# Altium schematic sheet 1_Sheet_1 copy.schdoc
size 302 x 215 mm; Name: A_A4; Symbol: a_a4; Device: A_A4; @Project Name: Quectel_EC200U_Board; REV: 1.1; Date: 11-07-24; Sheet: 1/1; Draw By: Anusha; Company: FervidSmart Solutions; Convert to PCB: yes; Add into BOM: yes; @Page No: 1; @Page Count: 3; @Schematic Name: Quectel_EC200U_Boost_Board; @Board Name: Quectel_EC200U_Boost_Board; @Update Date: 2025-06-19; @Create Time: 06:39:23; @Update Time: 12:09:43; @Page Name: Sheet_1 copy; @Create Date: 2025-06-19
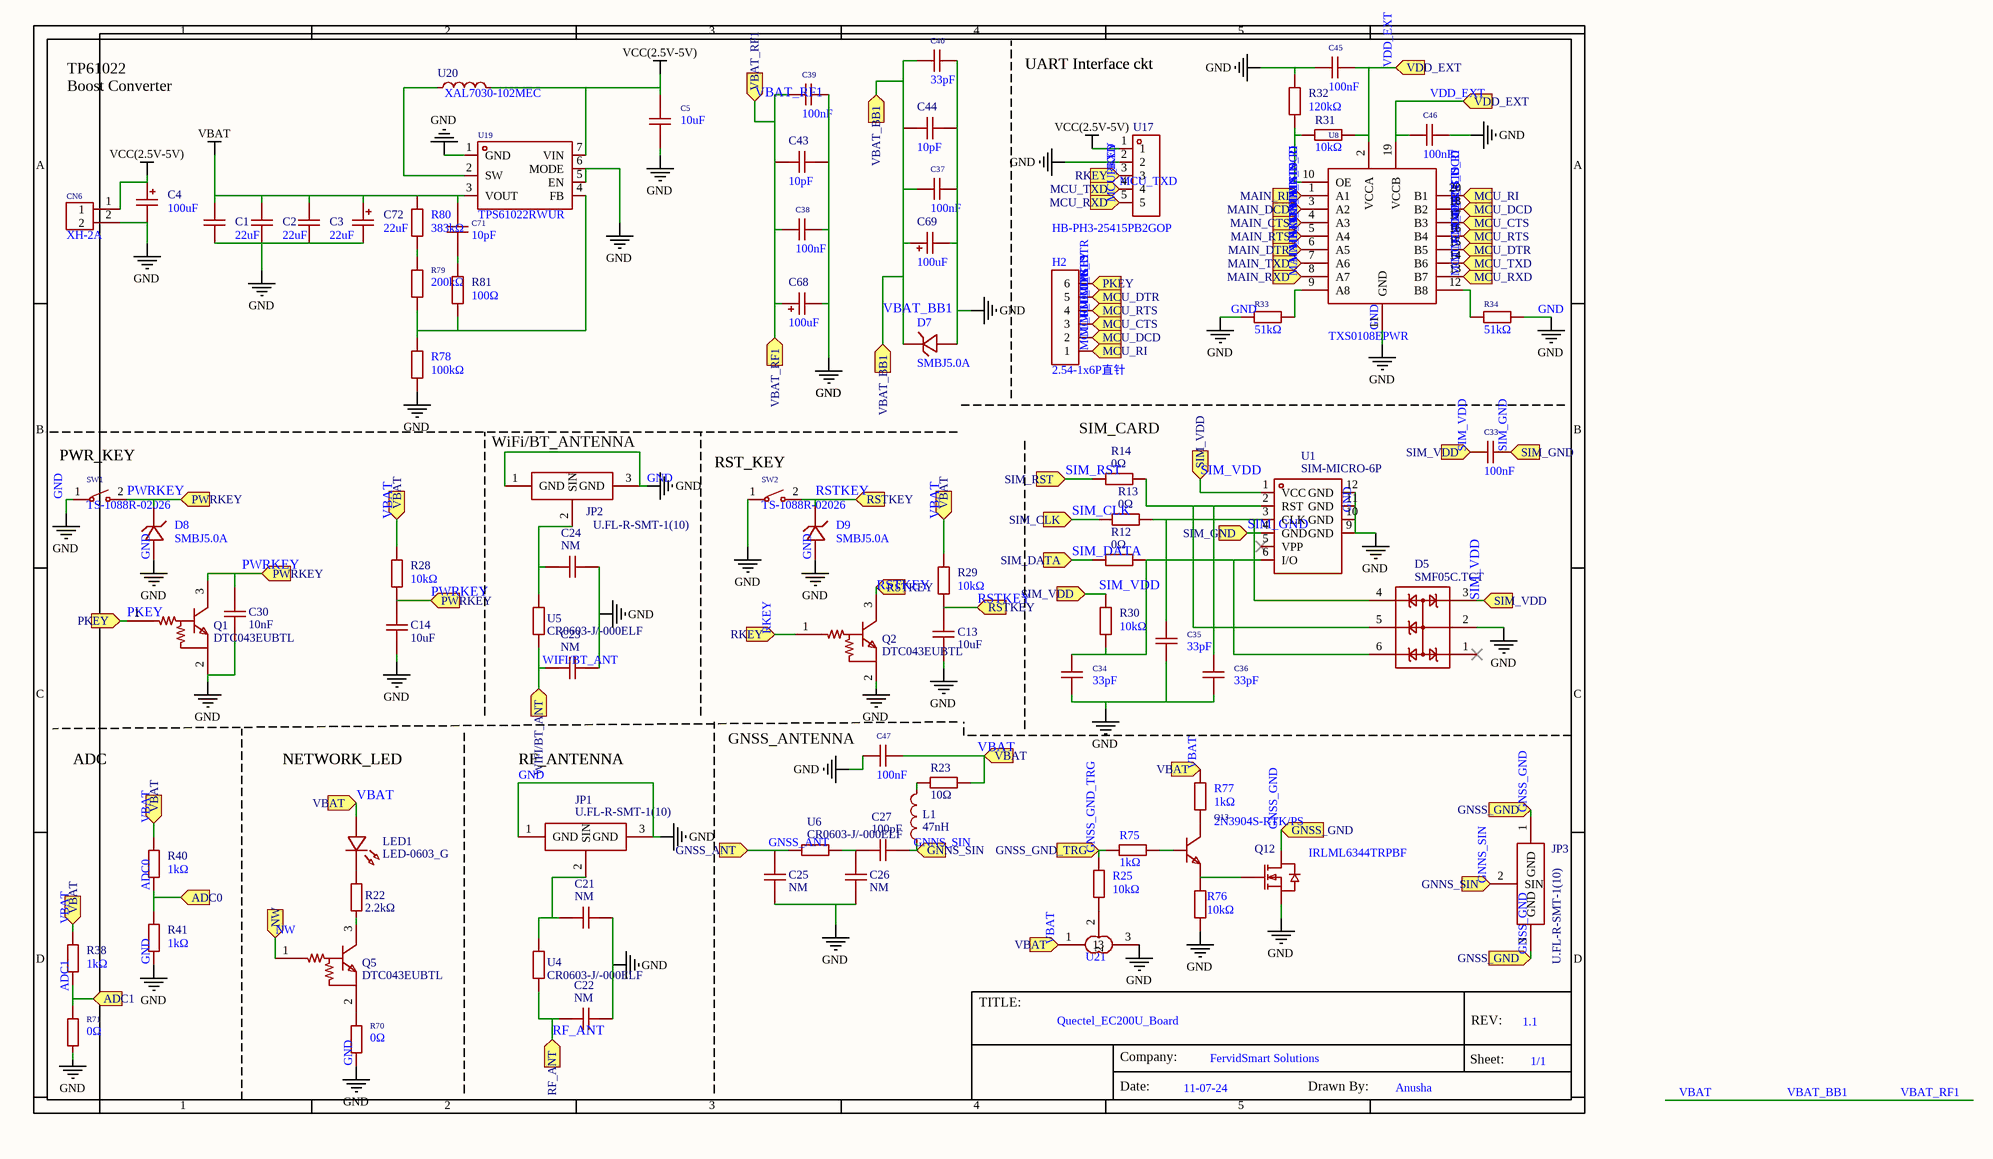
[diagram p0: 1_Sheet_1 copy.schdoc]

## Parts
C1  22uF  [C0805]
C2  22uF  [C0805]
C3  22uF  [C0805]
C4  100uF  [CASE-B_3528]
C5  10uF  [C0603]
C13  10uF  [C0603]
C14  10uF  [C0603]
C21  NM  [C0603]
C22  NM  [C0603]
C23  NM  [C0603]
C24  NM  [C0603]
C25  NM  [C0603]
C26  NM  [C0603]
C27  100pF  [C0603]
C30  10nF  [C0603]
C33  100nF  [C0603]
C34  33pF  [C0603]
C35  33pF  [C0603]
C36  33pF  [C0603]
C37  100nF  [C0603]
C38  100nF  [C0603]
C39  100nF  [C0603]
C40  33pF  [C0603]
C43  10pF  [C0603]
C44  10pF  [C0603]
C45  100nF  [C0603]
C46  100nF  [C0603]
C47  100nF  [C0603]
C68  100uF  [CASE-B_3528]
C69  100uF  [CASE-B_3528]
C71  10pF  [C0603]
C72  22uF  [CASE-A_3216]
CN6  XH-2A  [CONN-TH_XH-2A]
D5  SMF05C.TCT  [SC-70-6_L2.2-W1.3-P0.65-LS2.1-BR]
D7  SMBJ5.0A  [SMB_L4.6-W3.6-LS5.3-RD]
D8  SMBJ5.0A  [SMB_L4.6-W3.6-LS5.3-RD]
D9  SMBJ5.0A  [SMB_L4.6-W3.6-LS5.3-RD]
H2  2.54-1x6P直针  [HDR-TH_6P-P2.54-V-M-1]
JP1  U.FL-R-SMT-1(10)  [ANT-SMD_UFL-R-SMT-1-10]
JP2  U.FL-R-SMT-1(10)  [ANT-SMD_UFL-R-SMT-1-10]
JP3  U.FL-R-SMT-1(10)  [ANT-SMD_UFL-R-SMT-1-10]
L1  47nH  [IND-SMD_L1.6-W0.8-1]
LED1  LED-0603_G  [LED0603_GREEN]
Q1  DTC043EUBTL  [SOT-323-3_L2.0-W1.3-P1.30-LS2.1-BR]
Q2  DTC043EUBTL  [SOT-323-3_L2.0-W1.3-P1.30-LS2.1-BR]
Q5  DTC043EUBTL  [SOT-323-3_L2.0-W1.3-P1.30-LS2.1-BR]
Q12  IRLML6344TRPBF  [SOT-23-3_L2.9-W1.6-P1.90-LS2.8-BR]
Q13  2N3904S-RTK/PS  [SOT-23-3_L2.9-W1.3-P1.90-LS2.4-TR]
R12  0Ω  [R0603]
R13  0Ω  [R0603]
R14  0Ω  [R0603]
R22  2.2kΩ  [R0603]
R23  10Ω  [R0603]
R25  10kΩ  [R0603]
R28  10kΩ  [R0603]
R29  10kΩ  [R0603]
R30  10kΩ  [R0603]
R31  10kΩ  [R0603]
R32  120kΩ  [R0603]
R33  51kΩ  [R0603]
R34  51kΩ  [R0603]
R38  1kΩ  [R0603]
R40  1kΩ  [R0603]
R41  1kΩ  [R0603]
R70  0Ω  [R0603]
R71  0Ω  [R0603]
R75  1kΩ  [R0603]
R76  10kΩ  [R0603]
R77  1kΩ  [R0603]
R78  100kΩ  [R0402]
R79  200kΩ  [R0402]
R80  383kΩ  [R0402]
R81  100Ω  [R0402]
SW1  TS-1088R-02026  [SW-SMD_L3.9-W3.0-P4.45]
SW2  TS-1088R-02026  [SW-SMD_L3.9-W3.0-P4.45]
U1  SIM-MICRO-6P  [MICRO-SIM-SMD_KH-SIM1616-6PIN]
U4  CR0603-J/-000ELF  [R0603]
U5  CR0603-J/-000ELF  [R0603]
U6  CR0603-J/-000ELF  [R0603]
U8  TXS0108EPWR  [TSSOP-20_L6.5-W4.4-P0.65-LS6.4-BL]
U17  HB-PH3-25415PB2GOP  [HDR-TH_5P-P2.54-V-M]
U19  TPS61022RWUR  [VQFN-7_L2.0-W2.0-P0.55-TL_RWU]
U20  XAL7030-102MEC  [IND-SMD_L7.5-W7.5_XAL7030]
U21  (no value)  [threepointjumper]

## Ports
ADC0 (in), ADC1 (in), GNNS_SIN (in), GNSS_ANT (in), GNSS_GND (in), GNSS_GND_TRG (in), MAIN_CTS (in), MAIN_DCD (in), MAIN_DTR (in), MAIN_RI (in), MAIN_RTS (in), MAIN_RXD (in), MAIN_TXD (in), MCU_CTS (in), MCU_DCD (in), MCU_DTR (in), MCU_RI (in), MCU_RTS (in), MCU_RXD (in), MCU_TXD (in), NW (in), PKEY (in), PWRKEY (in), RF_ANT (in), RKEY (in), RSTKEY (in), SIM_CLK (in), SIM_DATA (in), SIM_GND (in), SIM_RST (in), SIM_VDD (in), VBAT (in), VBAT_BB1 (in), VBAT_RF1 (in), VDD_EXT (in), WIFI/BT_ANT (in)

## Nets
GND: C1.1 C2.1 C3.1 C4.2 C5.2 C13.2 C14.2 C21.2 C22.2 C23.2 C24.2 C25.2 C26.2 C30.1 C34.1 C35.1 C36.1 C37.1 C38.1 C39.1 C40.1 C43.1 C44.1 C45.2 C46.2 C47.1 C68.2 C69.2 C72.2 CN6.2 D5.2 D7.2 D8.2 D9.2 JP1.1(GND) JP1.3(GND) JP2.1(GND) JP2.3(GND) Q1.2(E) Q2.2(E) Q12.2(S) R32.2 R33.1 R34.2 R41.1 R70.1 R71.1 R76.2 R78.1 SW1.1 SW2.1 U1.9(GND) U1.10(GND) U1.11(GND) U1.12(GND) U8.11(GND) U17.2 U19.1(GND) U19.5(EN) U19.6(MODE) U21.3
VBAT: C1.2 C2.2 C3.2 C37.2 C38.2 C39.2 C40.2 C43.2 C44.2 C47.2 C68.1 C69.1 C71.2 C72.1 D7.1 LED1.1 R23.1 R28.2 R29.2 R38.2 R40.2 R77.1 R80.2 U19.3(VOUT) U21.1 ; port VBAT, port VBAT_BB1, port VBAT_RF1  [also labelled VBAT_BB1, VBAT_RF1]
VCC(2.5V-5V): C4.1 C5.1 CN6.1 U17.1 U19.7(VIN) U20.2
ADC0: R40.1 R41.2 ; port ADC0
ADC1: R38.1 R71.2 ; port ADC1
GNNS_SIN: C27.1 JP3.2(SIN) L1.1 ; port GNNS_SIN
GNSS_ANT: C25.1 U6.1 ; port GNSS_ANT
GNSS_GND: JP3.1(GND) JP3.3(GND) Q12.3(D) ; port GNSS_GND
GNSS_GND_TRG: R25.1 R75.1 ; port GNSS_GND_TRG
MAIN_CTS: U8.4(A3) ; port MAIN_CTS
MAIN_DCD: U8.3(A2) ; port MAIN_DCD
MAIN_DTR: U8.6(A5) ; port MAIN_DTR
MAIN_RI: U8.1(A1) ; port MAIN_RI
MAIN_RTS: U8.5(A4) ; port MAIN_RTS
MAIN_RXD: U8.8(A7) ; port MAIN_RXD
MAIN_TXD: U8.7(A6) ; port MAIN_TXD
MCU_CTS: H2.3 U8.17(B3) ; port MCU_CTS
MCU_DCD: H2.2 U8.18(B2) ; port MCU_DCD
MCU_DTR: H2.5 U8.15(B5) ; port MCU_DTR
MCU_RI: H2.1 U8.20(B1) ; port MCU_RI
MCU_RTS: H2.4 U8.16(B4) ; port MCU_RTS
MCU_RXD: U8.13(B7) U17.5 ; port MCU_RXD
MCU_TXD: U8.14(B6) U17.4 ; port MCU_TXD
NW: Q5.1(B) ; port NW
PKEY: H2.6 Q1.1(B) ; port PKEY
PWRKEY: C14.1 C30.2 D8.1 Q1.3(C) R28.1 SW1.2 ; port PWRKEY
RF_ANT: C22.1 U4.1 ; port RF_ANT
RKEY: Q2.1(B) U17.3 ; port RKEY
RSTKEY: C13.1 D9.1 Q2.3(C) R29.1 SW2.2 ; port RSTKEY
SIM_CLK: R13.1 ; port SIM_CLK
SIM_DATA: R12.1 ; port SIM_DATA
SIM_GND: C33.1 U1.4(GND) ; port SIM_GND
SIM_RST: R14.1 ; port SIM_RST
SIM_VDD: C33.2 D5.3 R30.2 U1.1(VCC) ; port SIM_VDD
VDD_EXT: C45.1 C46.1 R31.1 U8.2(VCCA) U8.19(VCCB) ; port VDD_EXT
WIFI/BT_ANT: C23.1 U5.1 ; port WIFI/BT_ANT
NetC21_1: C21.1 JP1.2(SIN) U4.2
NetC24_1: C24.1 JP2.2(SIN) U5.2
NetC26_1: C26.1 C27.2 U6.2
NetC34_2: C34.2 D5.6 R12.2 R30.1 U1.6(I/O)
NetC35_2: C35.2 D5.4 R13.2 U1.3(CLK)
NetC36_2: C36.2 D5.5 R14.2 U1.2(RST)
NetC71_1: C71.1 R81.2
NetL1_2: L1.2 R23.2
NetLED1_2: LED1.2 R22.1
NetQ5_2: Q5.2(E) R70.2
NetQ5_3: Q5.3(C) R22.2
NetQ12_1: Q12.1(G) Q13.1(E) R76.1
NetQ13_2: Q13.2(B) R75.2
NetQ13_3: Q13.3(C) R77.2
NetR25_2: R25.2 U21.2
NetR31_2: R31.2 R32.1 U8.10(OE)
NetR33_2: R33.2 U8.9(A8)
NetR34_1: R34.1 U8.12(B8)
NetR78_2: R78.2 R79.1 R81.1 U19.4(FB)
NetR79_2: R79.2 R80.1
NetU19_2: U19.2(SW) U20.1

Not connected (* = marked no-connect by the designer): D5 1*; U1 5(VPP)*

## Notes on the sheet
- TP61022
  Boost Converter
- UART Interface ckt
- (near R14) SIM_CARD
- (near SW1) PWR_KEY
- (near JP2) WiFi/BT_ANTENNA
- (near SW2) RST_KEY
- ADC
- NETWORK_LED
- RF_ANTENNA
- GNSS_ANTENNA

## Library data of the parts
C1-C3 = CL21A226MPQNNNE: Manufacturer: SAMSUNG(三星); Add into BOM: yes; Tolerance: ±20%
C4 = TAJB107M010RNJ: Manufacturer: Kyocera AVX; Add into BOM: yes; Tolerance: ±20%; Equivalent Series Resistance(ESR): 1.4Ω@100kHz
C5 = CL10A106KP8NNNC: Manufacturer: SAMSUNG(三星); Add into BOM: yes; Tolerance: ±10%
C13 C14 = CL10A106MP8NNNC: Manufacturer: SAMSUNG; Convert to PCB: yes
C21-C26 = VJ0603Y331JLJAJ32: Manufacturer: VISHAY(威世); Convert to PCB: yes
C27 = 0603N101G500CT: Manufacturer: Huaxin S&T; Convert to PCB: yes
C30 = 0603B103K250NT: Manufacturer: Guangdong Fenghua Advanced Tech; Convert to PCB: yes
C33 C37-C39 C45-C47 = CL10B104JB8NNNC: Manufacturer: SAMSUNG(三星); Add into BOM: yes; Tolerance: ±5%
C34-C36 C40 = CC0603JRNPO9BN330: Manufacturer: YAGEO(国巨); Add into BOM: yes; Tolerance: ±5%
C43 C44 = 0603CG100J500NT: Manufacturer: FH(风华); Add into BOM: yes; Tolerance: ±5%
C68 C69 = TAJB107K006RNJ: Manufacturer: Kyocera AVX; Add into BOM: yes; Tolerance: ±10%; Equivalent Series Resistance(ESR): 1.7Ω@100kHz
C71 = CC0603FRNPO9BN100: Manufacturer: YAGEO(国巨); Add into BOM: yes; Tolerance: ±1%
C72 = TAJA226K010RNJ: Manufacturer: Kyocera AVX; Add into BOM: yes; Tolerance: ±10%; Equivalent Series Resistance(ESR): 3Ω@100kHz
CN6 = XH-2A_C20079: Manufacturer: BOOMELE(博穆精密); Add into BOM: yes; Pins Structure: 1x2P; Pitch: 2.5mm; Reference Series: XH; Number of PINs Per Row: 2
D5 = SMF05C.TCT: Manufacturer: SEMTECH; Convert to PCB: yes
D7-D9 = SMBJ5.0A_C83333: Manufacturer: Littelfuse(美国力特); Add into BOM: yes; Reverse Stand-Off Voltage (Vrwm): 5V; Maximum Clamping Voltage: 9.2V; Peak Pulse Current (Ipp)@10/1000us: 65.3A; Peak Pulse Power Dissipation (Ppp)@10/1000us: 600W; Breakdown Voltage: 6.4V; Type: TVS
H2 = 2.54-1x6P直针: Manufacturer: BOOMELE(博穆精密); Symbol: Header-Male-2.54_1x6; Add into BOM: yes; Pin Structure: 1x6P; Pitch: 2.54mm; Circluar Pins/Square Pins: Square Pins; Current Rating (Max): 3A
JP1-JP3 = U.FL-R-SMT-1(10): Manufacturer: HRS; Convert to PCB: yes
L1 = LQW18AN47NJ00D: Manufacturer: MuRata; Convert to PCB: yes
LED1 = 19-217/GHC-YR1S2/3T: Manufacturer: EVERLIGHT(台湾亿光); Convert to PCB: yes
Q1 Q2 Q5 = DTC043EUBTL: Manufacturer: ROHM Semicon; Convert to PCB: yes
Q12 = IRLML6344TRPBF: Manufacturer: Infineon(英飞凌); Add into BOM: yes; Drain Source On Resistance (RDS(on)@Vgs,Id): 29mΩ@4.5V,5A; Gate Threshold Voltage (Vgs(th)@Id): 1.1V@10uA; Total Gate Charge (Qg@Vgs): 6.8nC@4.5V; Input Capacitance (Ciss@Vds): 650pF@25V
Q13 = 2N3904S-RTK/PS_C18536: Manufacturer: KEC; Add into BOM: yes; DC Current Gain (hFE@Ic,Vce): 100@10mA,1V; Transition Frequency (fT): 300MHz; Collector-Emitter Saturation Voltage (VCE(sat)@Ic,Ib): 300mV@50mA,5mA
R12-R14 = RK73Z1JTTD: Manufacturer: KOA; Resistance: 0; Convert to PCB: yes
R22 = RK73H1JTTD2201F: Manufacturer: KOA; Resistance: 2.2K; Convert to PCB: yes
R23 = CR0603FA10R0G: Manufacturer: LIZ; Resistance: 10; Convert to PCB: yes
R25 R76 = RC0603FR-0710KL: Manufacturer: YAGEO(国巨); Add into BOM: yes; Tolerance: ±1%; Temperature Coefficient: ±100ppm/℃
R28-R31 = ARG03BTC1002: Manufacturer: Viking(光颉); Add into BOM: yes; Tolerance: ±0.1%; Temperature Coefficient: ±25ppm/℃
R32 = 0603WAF1203T5E: Manufacturer: UNI-ROYAL(厚声); Add into BOM: yes; Tolerance: ±1%; Temperature Coefficient: ±100ppm/℃
R33 R34 = 0603WAF5102T5E: Manufacturer: UNI-ROYAL(厚声); Add into BOM: yes; Tolerance: ±1%; Temperature Coefficient: ±100ppm/℃
R38 R40 R41 = RT0603BRD071KL: Manufacturer: YAGEO(国巨); Add into BOM: no; Convert to PCB: yes; Tolerance: ±0.1%; Temperature Coefficient: ±25ppm/℃
R70 R71 = 0603WAF0000T5E: Manufacturer: UNI-ROYAL(厚声); Add into BOM: yes; Tolerance: ±1%
R75 R77 = RC0603FR-071KL: Manufacturer: YAGEO(国巨); Add into BOM: yes; Tolerance: ±1%; Temperature Coefficient: ±100ppm/℃
R78 = RC0402FR-07100KL: Manufacturer: YAGEO(国巨); Add into BOM: yes; Tolerance: ±1%; Temperature Coefficient: ±100ppm/℃
R79 = 0402WGF2003TCE: Manufacturer: UNI-ROYAL(厚声); Add into BOM: yes; Tolerance: ±1%; Temperature Coefficient: ±100ppm/℃
R80 = RK73H1ETTP3833F: Manufacturer: KOA; Add into BOM: yes; Tolerance: ±1%; Temperature Coefficient: ±100ppm/℃
R81 = 0402WGF1000TCE: Manufacturer: UNI-ROYAL(厚声); Add into BOM: yes; Tolerance: ±1%; Temperature Coefficient: ±200ppm/℃
SW1 SW2 = TS-1088R-02026: Manufacturer: XUNPU(讯普); Add into BOM: yes; Circuit: SPST; Actuator Style: Round Button; Switch Length: 3.9mm; Switch Width: 2.93mm; Switch Height: 2mm; Contact Current: 50mA; Voltage Rating (DC): 12V
U1 = SIM-MICRO-6P: Manufacturer: null; Convert to PCB: yes
U4-U6 = CR0603-J/-000ELF: Manufacturer: BOURNS; Resistance: 0Ω; Convert to PCB: yes
U8 = TXS0108EPWR: Manufacturer: TI(德州仪器); Add into BOM: yes; Channel Type: Bi-Directional; Data Rate: 60Mbps; Supply Voltage (VCCA): 1.4V~3.6V; Supply Voltage (VCCB): 1.65V~5.5V; Number of Circuits: 1; Channels per Circuit: 8; Output Type: Open Drain；Push-pull
U17 = HB-PH3-25415PB2GOP: Manufacturer: HANBO(汉博); Add into BOM: yes; Pin Structure: 1x5P; Pitch: 2.54mm; Circluar Pins/Square Pins: Square Pins; Current Rating (Max): 3A; Voltage Rating (Max): 250V; Soldering Temperature(Max): 260℃
U19 = TPS61022RWUR: Manufacturer: TI(德州仪器); Add into BOM: yes; Function: boost converterType; Output Type: Adjustable; Input Voltage: 500mV~5.5V; Output Voltage: 2.2V~5.5V; Switching Frequency: 1MHz；600kHz; Number of Outputs: 1; Topology: Boost; Switch tube (built-in/external): 内置
U20 = XAL7030-102MEC: Manufacturer: Coilcraft(线艺); Add into BOM: yes
U21 = threepinjump: Add into BOM: yes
